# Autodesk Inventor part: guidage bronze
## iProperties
Created: 2011-09
Part Number: guidage bronze
Document SubType Name: Modeling
Designer: Dominique
Author: Dominique
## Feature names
1. Extrusion1
2. Extrusion2
3. Révolution1 [Revolution]
